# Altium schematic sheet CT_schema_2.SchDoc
size 276 x 169 mm
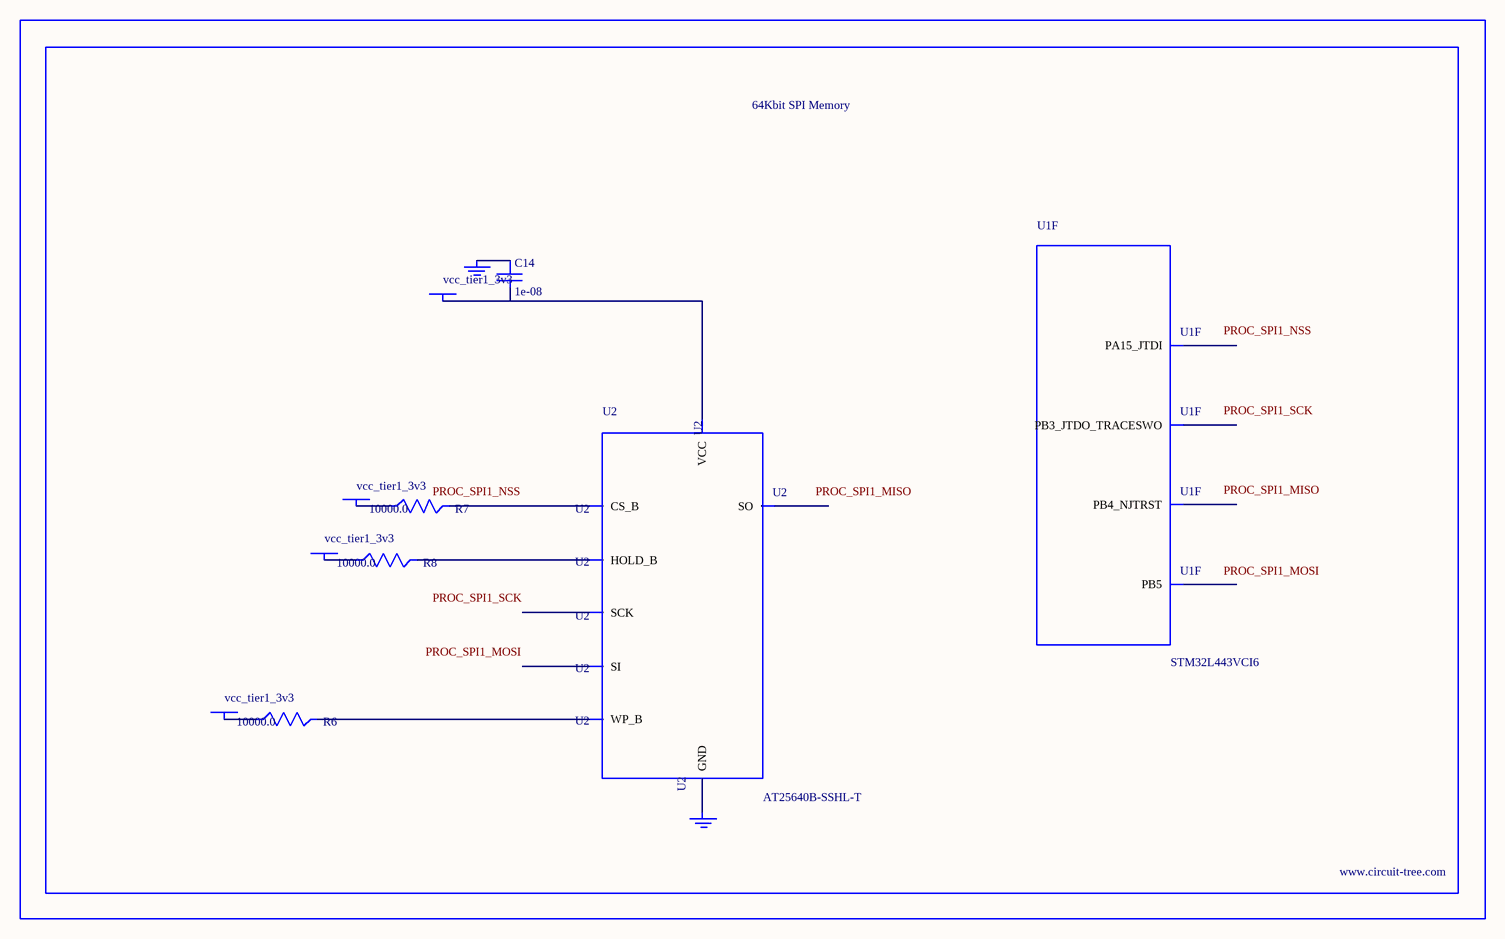
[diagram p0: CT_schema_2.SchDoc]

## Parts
BORDER1  (no value)
C14  1e-08  [C0402]
GND_INSTANCE_1_0  (no value)
GND_INSTANCE_1_1  (no value)
POWER_INSTANCE_1_0  vcc_tier1_3v3
POWER_INSTANCE_1_1  vcc_tier1_3v3
POWER_INSTANCE_1_2  vcc_tier1_3v3
POWER_INSTANCE_1_3  vcc_tier1_3v3
R6  10000.0  [R0603]
R7  10000.0  [R0603]
R8  10000.0  [R0603]
U1  STM32L443VCI6  [UFBGA100]  (part F of 7)
U2  AT25640B-SSHL-T  [SOIC-8]

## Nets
NetC14_1: C14.1 GND_INSTANCE_1_0.0(GND)
NetC14_2: C14.2 POWER_INSTANCE_1_3.0(PWR) U2.8(VCC)
NetGND_INSTANCE_1_1_0: GND_INSTANCE_1_1.0(GND) U2.4(GND)
NetPOWER_INSTANCE_1_0_0: POWER_INSTANCE_1_0.0(PWR) R7.1
NetPOWER_INSTANCE_1_1_0: POWER_INSTANCE_1_1.0(PWR) R6.1
NetPOWER_INSTANCE_1_2_0: POWER_INSTANCE_1_2.0(PWR) R8.1
NetR6_2: R6.2 U2.3(WP_B)
NetR7_2: R7.2 U2.1(CS_B)
NetR8_2: R8.2 U2.7(HOLD_B)

Not connected (* = marked no-connect by the designer): U1 A7(PB4_NJTRST) A8(PB3_JTDO_TRACESWO) A9(PA15_JTDI) C5(PB5); U2 2(SO) 5(SI) 6(SCK)

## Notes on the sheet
- Labels drawn without touching a wire or pin: PROC_SPI1_MISO, PROC_SPI1_MOSI, PROC_SPI1_NSS, PROC_SPI1_SCK

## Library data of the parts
BORDER1 = BORDER_PAGE1
C14 = C0402C103K3RAC
GND_INSTANCE_1_0 GND_INSTANCE_1_1 = GND
POWER_INSTANCE_1_0-POWER_INSTANCE_1_3 = PWR
R6-R8 = RC0603JR-0710KL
